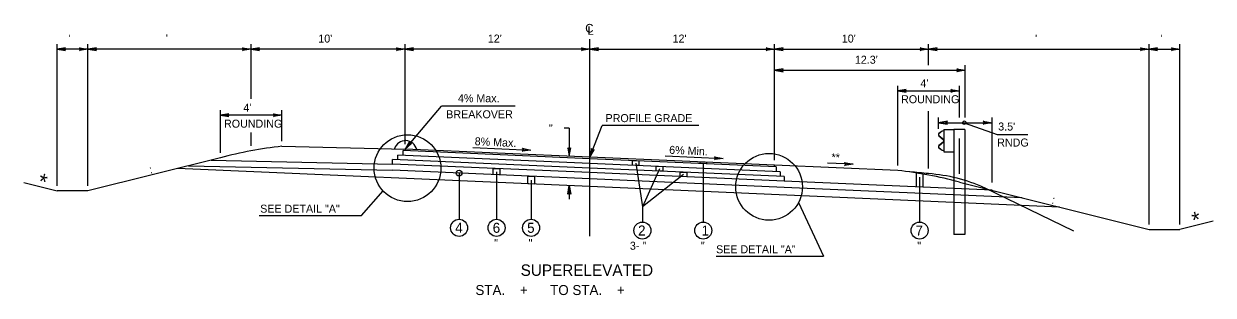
# Model space of a CAD drawing. Extents: x -540 to 1231, y -564 to 421.
# Drawn here: x 1023.3 to 1231.4, y -301.4 to -253.9 of the extents above; entities that cross this region are included whole.
import ezdxf

# ---------------------------------------------------------------- set-up
doc = ezdxf.new("R2010")
doc.units = 0
doc.layers.add('1', color=7, linetype='Continuous')
doc.layers.add('Des_ Drain_ Ftrs', color=7, linetype='Continuous')

msp = doc.modelspace()

# ---------------------------------------------------------------- linework, layer by layer
at = {"layer": '1'}
for p, q in [((1029.15, -282.3), (1029.15, -257.5)), ((1034.54, -282.3), (1034.54, -257.5)), ((1063.11, -267.07), (1063.11, -257.5)), ((1090.05, -274.97), (1090.05, -257.5)), ((1122.38, -291.11), (1122.38, -256.62)), ((1154.71, -277.79), (1154.71, -257.5)), ((1181.65, -261.2), (1181.65, -257.5)), ((1220.23, -289.04), (1220.23, -257.5)), ((1225.62, -289.04), (1225.62, -257.5)), ((1034.54, -258.38), (1029.15, -258.38)), ((1063.11, -258.38), (1034.54, -258.38)), ((1090.05, -258.38), (1063.11, -258.38)), ((1122.38, -258.38), (1090.05, -258.38)), ((1122.38, -258.38), (1154.71, -258.38)), ((1154.71, -258.38), (1181.65, -258.38)), ((1181.65, -258.38), (1220.23, -258.38)), ((1220.23, -258.38), (1225.62, -258.38)), ((1154.7, -262.08), (1188.07, -262.08)), ((1188.07, -270.36), (1188.07, -261.2)), ((1176.26, -278.73), (1176.26, -264.78)), ((1176.26, -265.66), (1187.04, -265.66)), ((1187.04, -270.36), (1187.04, -264.78)), ((1090.04, -275.85), (1096.39, -268.37)), ((1109.32, -268.37), (1096.39, -268.37)), ((1057.72, -276.51), (1057.72, -269.04)), ((1068.49, -269.92), (1057.72, -269.92)), ((1068.49, -274.49), (1068.49, -269.04)), ((1181.65, -279.27), (1181.65, -269.23)), ((1183.38, -272.31), (1183.38, -270.36)), ((1192.77, -281.72), (1192.77, -270.36)), ((1118.78, -272.22), (1117.9, -272.22)), ((1118.78, -272.22), (1118.78, -277.1)), ((1122.38, -277.26), (1124.51, -271.73)), ((1141.43, -271.73), (1124.51, -271.73)), ((1183.38, -271.24), (1192.77, -271.24)), ((1184.33, -272.42), (1184.33, -276.36)), ((1184.33, -272.42), (1186.08, -272.42)), ((1186.08, -272.42), (1186.08, -290.82)), ((1187.97, -272.42), (1186.08, -272.42)), ((1187.9, -271.24), (1193.66, -273.31)), ((1187.97, -272.42), (1187.97, -290.82)), ((1063.11, -275.27), (1063.11, -272.98)), ((1183.45, -273.53), (1184.21, -274.17)), ((1184.21, -274.62), (1183.45, -275.25)), ((1184, -272.71), (1183.47, -273.1)), ((1183.47, -273.51), (1184.23, -274.14)), ((1184.23, -274.64), (1183.47, -275.27)), ((1184.02, -272.74), (1183.48, -273.12)), ((1184.33, -272.65), (1184, -272.71)), ((1184.33, -272.68), (1184.02, -272.74)), ((1184.3, -274.35), (1184.3, -274.43)), ((1184.33, -274.35), (1184.33, -274.43)), ((1187.04, -280.18), (1187.04, -274.03)), ((1193.66, -273.31), (1199.01, -273.31)), ((1068.49, -275.37), (1090.04, -275.85)), ((1122.38, -277.56), (1089.7, -276.13)), ((1089.7, -276.94), (1089.7, -276.13)), ((1122.38, -277.26), (1090.04, -275.85)), ((1090.04, -275.85), (1090.04, -276.15)), ((1101.92, -275.59), (1112.03, -276.03)), ((1183.47, -275.68), (1184, -276.07)), ((1183.48, -275.66), (1184.02, -276.05)), ((1184, -276.07), (1184.33, -276.13)), ((1184.02, -276.05), (1184.33, -276.1)), ((1184.33, -276.36), (1186.08, -276.36)), ((1057.72, -277.39), (1034.54, -283.18)), ((1052.16, -278.78), (1087.86, -279.56)), ((1056.12, -277.78), (1087.86, -278.48)), ((1122.38, -279.18), (1087.86, -277.67)), ((1087.86, -278.48), (1087.86, -277.67)), ((1122.38, -279.98), (1087.86, -278.48)), ((1122.38, -278.37), (1088.78, -276.9)), ((1088.78, -277.71), (1088.78, -276.9)), ((1154.71, -278.67), (1122.38, -277.26)), ((1154.95, -278.98), (1122.38, -277.56)), ((1155.65, -279.82), (1122.38, -278.37)), ((1130.4, -278.3), (1131.56, -285.93)), ((1135.57, -277.06), (1145.68, -277.51)), ((1142.22, -278.29), (1142.22, -288.61)), ((1176.26, -279.61), (1154.71, -278.67)), ((1154.71, -278.97), (1154.71, -278.67)), ((1168.44, -278.52), (1163.94, -278.33)), ((1122.38, -282.41), (1050.22, -279.26)), ((1122.38, -281.06), (1087.86, -279.56)), ((1099.49, -280.06), (1099.49, -288.14)), ((1106.05, -279.81), (1106.05, -288.14)), ((1156.35, -280.66), (1122.38, -279.18)), ((1156.35, -281.47), (1122.38, -279.98)), ((1134.57, -279.29), (1131.56, -285.93)), ((1138.75, -280.3), (1131.56, -285.93)), ((1154.95, -278.98), (1154.95, -279.79)), ((1155.65, -279.82), (1155.65, -280.63)), ((1156.35, -280.66), (1156.35, -281.47)), ((1180.08, -280.77), (1180.08, -288.61)), ((1183.38, -280.37), (1183.38, -280.37)), ((1023.32, -281.72), (1029.15, -283.18)), ((1112.09, -281.28), (1112.09, -288.14)), ((1118.78, -282.25), (1118.78, -284.62)), ((1156.35, -282.55), (1122.38, -281.06)), ((1204.55, -286), (1122.38, -282.41)), ((1192.79, -283.06), (1156.35, -281.47)), ((1198.02, -284.37), (1156.35, -282.55)), ((1187.04, -281.62), (1220.23, -289.92)), ((1191.39, -282.6), (1207, -290.13)), ((1034.54, -283.18), (1029.15, -283.18)), ((1082.44, -287.48), (1086.18, -283.16)), ((1131.56, -285.93), (1131.56, -288.61)), ((1158.88, -285.18), (1163.24, -294.58)), ((1064.51, -287.48), (1082.44, -287.48)), ((1231.45, -288.46), (1225.62, -289.92)), ((1187.97, -290.82), (1186.08, -290.82)), ((1220.23, -289.92), (1225.62, -289.92)), ((1144.45, -294.58), (1163.24, -294.58))]:
    msp.add_line(p, q, dxfattribs=at)
for points in [[(1129.82, -277.88), (1130.97, -277.93), (1130.97, -278.74), (1129.82, -278.69)], [(1134, -278.87), (1135.15, -278.92), (1135.15, -279.73), (1134, -279.68)], [(1141.65, -278.1), (1142.8, -278.15), (1142.8, -278.45), (1141.65, -278.4)], [(1105.48, -279.25), (1106.62, -279.3), (1106.62, -280.38), (1105.48, -280.32)], [(1111.51, -280.59), (1112.66, -280.64), (1112.66, -281.99), (1111.51, -281.94)], [(1138.17, -279.87), (1139.32, -279.92), (1139.32, -280.72), (1138.17, -280.67)], [(1179.54, -280.03), (1180.61, -280.2), (1180.61, -282.53), (1179.54, -282.48)]]:
    msp.add_lwpolyline(points, close=True, dxfattribs=at)
for centre, radius in [((1090.47, -279.2), 5.84), ((1153.73, -282.45), 5.84), ((1099.49, -280.06), 0.5), ((1099.49, -289.63), 1.49), ((1106.05, -289.63), 1.49), ((1112.09, -289.63), 1.49), ((1131.56, -290.1), 1.49), ((1142.22, -290.1), 1.49), ((1180.08, -290.1), 1.49)]:
    msp.add_circle(centre, radius, dxfattribs=at)
for centre, radius, start, end in [((1090.12, -276.38), 2, 12.9578, 163.1611), ((1075.39, -342.21), 67.19, 95.8911, 105.2497), ((1169.37, -346.45), 67.19, 74.7602, 84.1188)]:
    msp.add_arc(centre, radius, start, end, dxfattribs=at)
msp.add_ellipse((1187.9, -271.24), major_axis=(-0.311, 0), ratio=0.964041, dxfattribs=at)
for centre, major_axis, start_param, end_param in [((1183.64, -273.32), (-0.288, 0), 5.35781, 7.138763), ((1183.64, -273.32), (-0.258, 0), 5.35781, 7.138763), ((1184.04, -274.35), (0.258, 0), 0, 0.855848), ((1184.04, -274.43), (0.258, 0), 5.427337, 6.283185), ((1184.04, -274.35), (0.288, 0), 0, 0.855848), ((1184.04, -274.43), (0.288, 0), 5.427337, 6.283185), ((1183.64, -275.46), (-0.288, 0), 5.427608, 7.208561), ((1183.64, -275.46), (-0.258, 0), 5.427608, 7.208561), ((1170.42, -380.81), (105.02, 0), 1.463691, 1.495354), ((1179.45, -307.44), (28.39, 0), 1.136862, 1.493152)]:
    msp.add_ellipse(centre, major_axis=major_axis, ratio=0.964041, start_param=start_param, end_param=end_param, dxfattribs=at)
at = {"layer": 'Des_ Drain_ Ftrs'}
for points in [[(1029.15, -258.38), (1030.64, -258.63), (1030.34, -258.38), (1030.64, -258.13)], [(1034.54, -258.38), (1033.05, -258.63), (1033.34, -258.38), (1033.05, -258.13)], [(1034.54, -258.38), (1036.03, -258.63), (1035.73, -258.38), (1036.03, -258.13)], [(1063.11, -258.38), (1061.62, -258.63), (1061.91, -258.38), (1061.62, -258.13)], [(1063.11, -258.38), (1064.59, -258.63), (1064.3, -258.38), (1064.59, -258.13)], [(1090.05, -258.38), (1088.56, -258.63), (1088.85, -258.38), (1088.56, -258.13)], [(1090.05, -258.38), (1091.54, -258.63), (1091.24, -258.38), (1091.54, -258.13)], [(1122.38, -258.38), (1120.89, -258.63), (1121.18, -258.38), (1120.89, -258.13)], [(1122.38, -258.38), (1123.86, -258.63), (1123.57, -258.38), (1123.86, -258.13)], [(1154.71, -258.38), (1153.22, -258.63), (1153.51, -258.38), (1153.22, -258.13)], [(1154.71, -258.38), (1156.19, -258.63), (1155.9, -258.38), (1156.19, -258.13)], [(1181.65, -258.38), (1180.16, -258.63), (1180.45, -258.38), (1180.16, -258.13)], [(1181.65, -258.38), (1183.14, -258.63), (1182.84, -258.38), (1183.14, -258.13)], [(1220.23, -258.38), (1218.75, -258.63), (1219.04, -258.38), (1218.75, -258.13)], [(1220.23, -258.38), (1221.72, -258.63), (1221.43, -258.38), (1221.72, -258.13)], [(1225.62, -258.38), (1224.13, -258.63), (1224.43, -258.38), (1224.13, -258.13)], [(1154.7, -262.08), (1156.19, -262.33), (1155.9, -262.08), (1156.19, -261.84)], [(1188.07, -262.08), (1186.58, -262.33), (1186.88, -262.08), (1186.58, -261.84)], [(1176.26, -265.66), (1177.75, -265.91), (1177.45, -265.66), (1177.75, -265.41)], [(1187.04, -265.66), (1185.55, -265.91), (1185.84, -265.66), (1185.55, -265.41)], [(1057.72, -269.92), (1059.21, -270.17), (1058.91, -269.92), (1059.21, -269.68)], [(1068.49, -269.92), (1067.01, -270.17), (1067.3, -269.92), (1067.01, -269.68)], [(1183.38, -271.24), (1184.93, -271.49), (1184.62, -271.24), (1184.93, -270.99)], [(1192.77, -271.24), (1191.22, -271.49), (1191.53, -271.24), (1191.22, -270.99)], [(1090.04, -275.85), (1091.19, -274.87), (1090.81, -274.94), (1090.81, -274.55)], [(1112.03, -276.03), (1110.54, -276.21), (1110.84, -275.98), (1110.56, -275.72)], [(1118.78, -277.1), (1119.03, -275.61), (1118.78, -275.91), (1118.53, -275.61)], [(1122.38, -277.26), (1123.14, -275.96), (1122.8, -276.14), (1122.68, -275.78)], [(1145.68, -277.51), (1144.18, -277.69), (1144.49, -277.45), (1144.2, -277.19)], [(1168.44, -278.52), (1166.94, -278.71), (1167.24, -278.47), (1166.96, -278.21)], [(1118.78, -282.25), (1119.03, -283.74), (1118.78, -283.45), (1118.53, -283.74)]]:
    msp.add_lwpolyline(points, close=True, dxfattribs=at)

# ---------------------------------------------------------------- texts
at = {"layer": '1'}
for s, height, p in [(" '", 1.4, (1030.65, -257.23)), ("  '", 1.4, (1047.13, -257.16)), ("10'", 1.4, (1074.86, -257.23)), ("12'", 1.4, (1104.52, -257.23)), ("12'", 1.4, (1136.85, -257.23)), ("10'", 1.4, (1166.46, -257.23)), ("  '", 1.4, (1199.24, -257.23)), (" '", 1.4, (1221.73, -257.23)), ("12.3'", 1.4, (1168.75, -260.93)), ("4'", 1.4, (1180.22, -265.04)), ('4% Max.', 1.4, (1099.29, -267.67)), ("4'", 1.4, (1061.75, -269.31)), ('ROUNDING', 1.4, (1176.83, -267.84)), ('BREAKOVER', 1.4, (1097.24, -270.47)), ('PROFILE GRADE', 1.4, (1125.12, -271.14)), ('ROUNDING', 1.4, (1058.36, -272.11)), ("3.5'", 1.4, (1193.83, -272.61)), ('RNDG', 1.4, (1193.65, -275.41)), ('SEE DETAIL "A"', 1.4, (1064.69, -286.98)), ('4', 1.75, (1098.81, -290.5)), ('6', 1.75, (1105.38, -290.5)), ('5', 1.75, (1111.4, -290.5)), ('2', 1.75, (1130.81, -290.97)), ('1', 1.75, (1141.92, -290.97)), ('7', 1.75, (1179.36, -290.97)), (' "', 1.4, (1105.11, -292.99)), (' "', 1.4, (1111.14, -292.99)), ('3- "', 1.4, (1129.38, -293.46)), (' "', 1.4, (1141.28, -293.46)), ('SEE DETAIL "A"', 1.4, (1144.46, -294.08)), ('  "', 1.4, (1178.63, -293.46)), ('SUPERELEVATED', 2, (1110.26, -298.03)), ('STA.    +      TO STA.    +     ', 1.75, (1102.35, -301.38))]:
    msp.add_text(s, height=height, dxfattribs=at).set_placement(p)
for s, height, rotation, p in [('  "', 1.4, 0.1438, (1114.17, -272.92)), ('8% Max.', 1.4, 357.3762, (1102.2, -275.17)), ('6% Min.', 1.4, 357.3731, (1136.23, -276.67)), ('**', 1.4, 357.2158, (1164.62, -277.96)), ('*', 2.8, 347.1521, (1025.63, -282.75)), (' : ', 1.4, 14.2282, (1044.95, -280.3)), (' : ', 1.4, 345.7718, (1202.58, -285.22)), ('*', 2.8, 12.8479, (1228.08, -289.73))]:
    msp.add_text(s, height=height, rotation=rotation, dxfattribs=at).set_placement(p)
at = {"layer": 'Des_ Drain_ Ftrs'}
for s, p in [('C', (1121.56, -255.47)), ('L', (1121.96, -255.87))]:
    msp.add_text(s, height=1.5, dxfattribs=at).set_placement(p)

doc.saveas('drawing.dxf')
